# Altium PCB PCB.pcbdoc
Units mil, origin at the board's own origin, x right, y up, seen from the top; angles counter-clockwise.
Board outline 3858.27 x 1594.49 mil, 2 copper layers (Top Layer, Bottom Layer); 30 components, 23 nets, 84 pads, 0 vias.
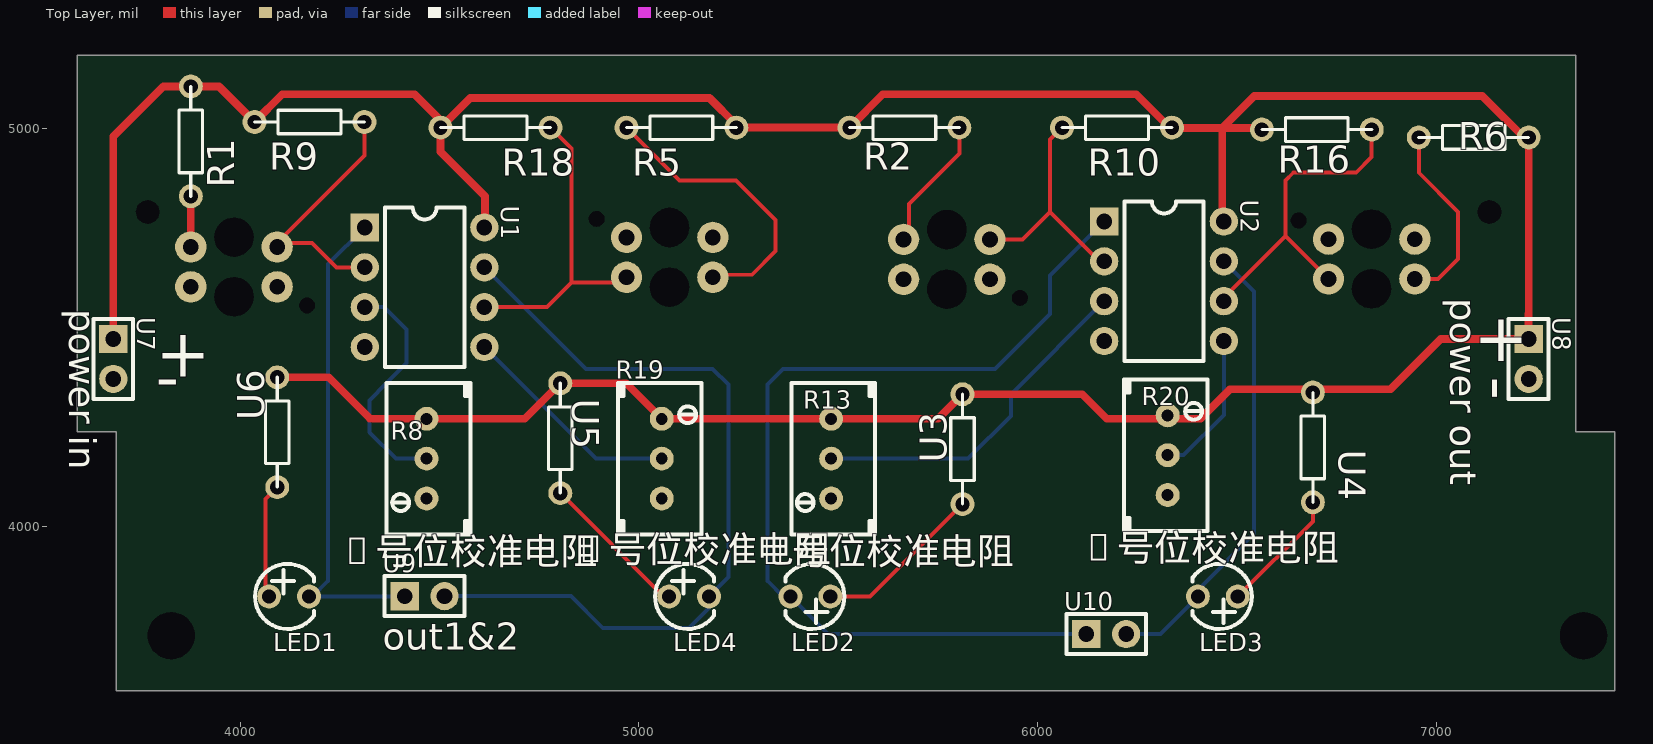
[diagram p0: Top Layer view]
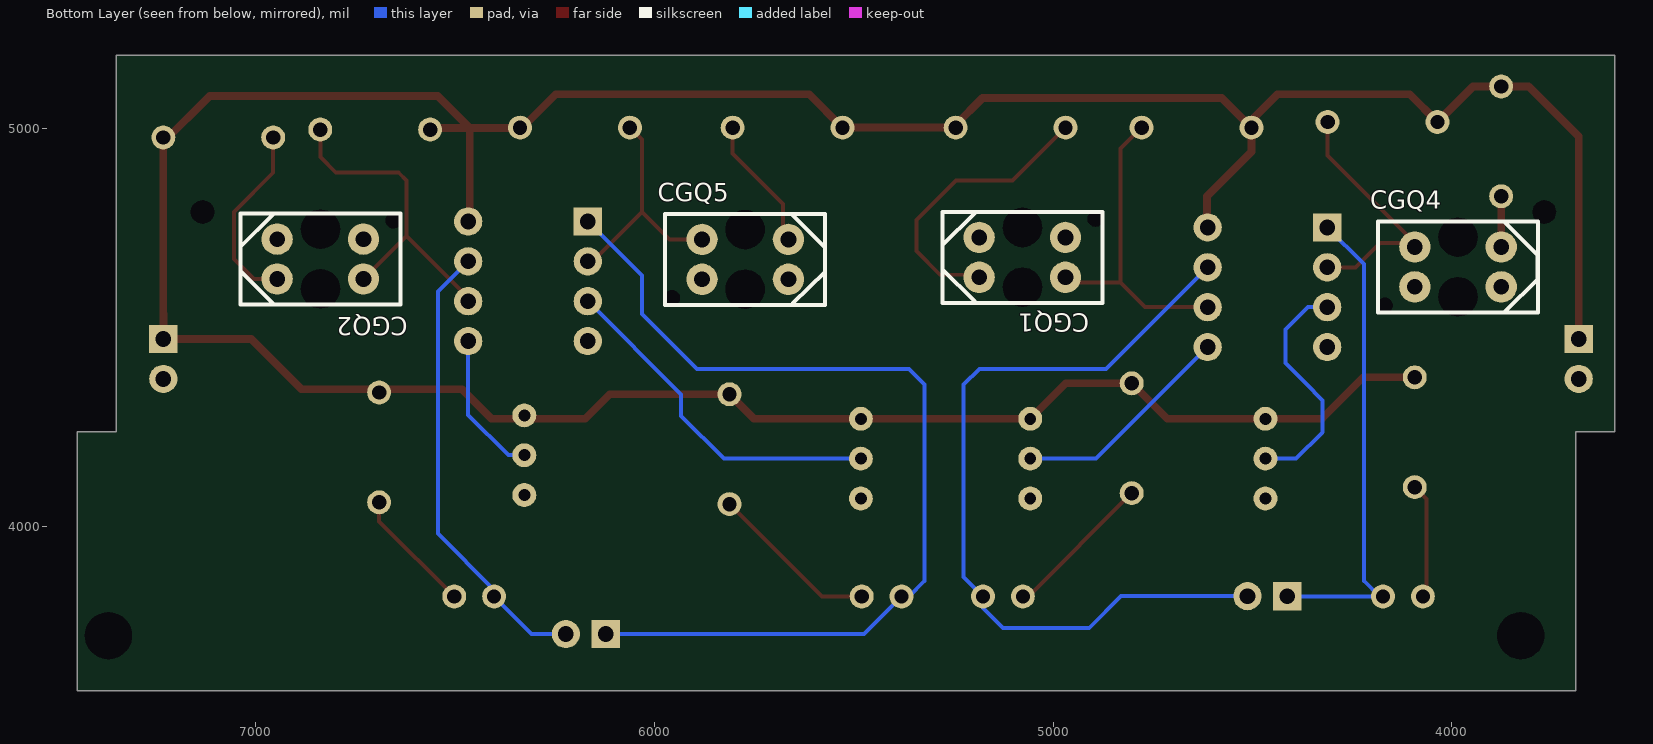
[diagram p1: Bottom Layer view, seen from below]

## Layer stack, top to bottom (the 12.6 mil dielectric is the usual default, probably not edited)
Top Solder: solder mask 0.4, Solder Resist, Dk 3.5
Top Layer: signal copper 1.4
Dielectric 1: dielectric 12.6, FR-4, Dk 4.8
Bottom Layer: signal copper 1.4
Bottom Solder: solder mask 0.4, Solder Resist, Dk 3.5

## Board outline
3590.55,5183.46 7350.39,5183.46 7350.39,4238.58 7448.82,4238.58 7448.82,3588.97 3688.98,3588.97 3688.98,4238.58 3590.55,4238.58
cut-out: 3885.83,3726.77 ccw(c3826.77,3726.77) 3767.72,3726.77 ccw(c3826.77,3726.77)
cut-out: 7429.13,3726.77 ccw(c7370.08,3726.77) 7311.02,3726.77 ccw(c7370.08,3726.77)
cut-out: 3797.24,4789.76 ccw(c3767.72,4789.76) 3738.19,4789.76 ccw(c3767.72,4789.76)
cut-out: 7163.39,4789.76 ccw(c7133.86,4789.76) 7104.33,4789.76 ccw(c7133.86,4789.76)

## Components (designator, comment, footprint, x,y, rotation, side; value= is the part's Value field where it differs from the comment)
CGQ1 "" opto-th_tcrt5000l 5077.44,4675.9 r0 bottom
CGQ2 "" opto-th_tcrt5000l 6838.58,4671.65 r0 bottom
CGQ4 "" opto-th_tcrt5000l 3984.25,4651.96 r180 bottom
CGQ5 "" opto-th_tcrt5000l 5772.44,4670.9 r180 bottom
LED1 "" led-th_bd3.8-p2.54-fd 4122.44,3825.19 r0 top
LED2 "" led-th_bd3.8-p2.54-fd 5430.31,3825.19 r180 top
LED3 "" led-th_bd3.8-p2.54-fd 6452.44,3825.19 r180 top
LED4 "" led-th_bd3.8-p2.54-fd 5125.98,3825.19 r0 top
R1 "" 直插电阻 3905.51,5045.66 r270 top
R2 "" 直插电阻 5587.44,5030.9 r0 top
R5 "" 直插电阻 5027.98,5030.9 r0 top
R6 "" 直插电阻 7015.75,5006.29 r0 top
R8 "1号位校准电阻" res-adj-th_3296w 4467.44,4170.9 r180 top
R9 "" 直插电阻 4252.44,4985.9 r180 top
R10 "" 直插电阻 6120.84,5030.9 r0 top
R13 "3号位校准电阻" res-adj-th_3296w 5482.44,4170.9 r180 top
R16 "" 直插电阻 6622.05,5025.98 r0 top
R18 "" 直插电阻 4561.56,5030.9 r0 top
R19 "2号位校准电阻" res-adj-th_3296w 5057.44,4170.9 r0 top
R20 "4号位校准电阻" res-adj-th_3296w 6326.77,4179.52 r0 top
U1 "" dip-8_l9.7-w6.4-p2.54-ls7.6-bl 4462.44,4600.9 r270 top
U2 "" dip-8_l9.7-w6.4-p2.54-ls7.6-bl 6317.44,4615.9 r270 top
U3 "" 直插电阻 5782.44,4115.9 r90 top
U4 "" 直插电阻 6720.47,4277.95 r270 top
U5 "" 直插电阻 4832.44,4300.9 r270 top
U6 "" 直插电阻 4122.44,4315.9 r270 top
U7 "power in" hdr-th_2p-p2.54-v-m-1 3681.5,4420.9 r270 top
U8 "power out" hdr-th_2p-p2.54-v-m-1 7232.28,4420.9 r270 top
U9 "out1&2" hdr-th_2p-p2.54-v-m-1 4462.44,3825.9 r0 top
U10 "" hdr-th_2p-p2.54-v-m-1 6172.44,3730.9 r0 top

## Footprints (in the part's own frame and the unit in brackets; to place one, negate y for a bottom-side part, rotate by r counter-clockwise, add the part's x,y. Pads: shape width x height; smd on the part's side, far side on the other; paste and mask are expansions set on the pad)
dip-8_l9.7-w6.4-p2.54-ls7.6-bl [mil]
  rect 70.9x70.9 hole 39.4: 1(-150,-150)
  round 70.9 hole 39.4: 2(-50,-150) 3(50,-150) 4(150,-150) 5(150,150) 6(50,150) 7(-50,150) 8(-150,150)
  silkscreen extent -200,-100 200,100
hdr-th_2p-p2.54-v-m-1 [mm]
  rect 1.8x1.8 hole 1: 1(-1.27,0)
  round 1.8 hole 1: 2(1.27,0)
  silkscreen extent -2.54,-1.27 2.54,1.27
led-th_bd3.8-p2.54-fd [mil]
  round 60 hole 35.43: 1(-50,0) 2(50,0)
  silkscreen extent -85,-82 63,82
opto-th_tcrt5000l [mil]
  round 78.7 hole 39.4: 1(-108.3,50) 2(-108.3,-50) 3(108.3,50) 4(108.3,-50)
  Multi-Layer board cut-out: 48.9,74.7 48.9,74.7 44.03,53.35 30.38,36.23 10.65,26.73 -11.25,26.73 -30.98,36.23 -44.63,53.35 -49.5,74.7 -49.5,74.7 -44.63,96.05 -30.98,113.17 -11.25,122.67 10.65,122.67 30.38,113.17 44.03,96.05 48.9,74.7
  Multi-Layer board cut-out: 48.9,-74.9 48.9,-74.9 44.03,-96.25 30.38,-113.37 10.65,-122.87 -11.25,-122.87 -30.98,-113.37 -44.63,-96.25 -49.5,-74.9 -49.5,-74.9 -44.63,-53.55 -30.98,-36.43 -11.25,-26.93 10.65,-26.93 30.38,-36.43 44.03,-53.55 48.9,-74.9
  Multi-Layer board cut-out: -163.7,-96.6 -163.7,-96.6 -165.65,-105.15 -171.12,-112 -179.02,-115.81 -187.78,-115.81 -195.68,-112 -201.15,-105.15 -203.1,-96.6 -203.1,-96.6 -201.15,-88.05 -195.68,-81.2 -187.78,-77.39 -179.02,-77.39 -171.12,-81.2 -165.65,-88.05 -163.7,-96.6
  silkscreen extent -201,-114 200,114
res-adj-th_3296w [mil]
  round 60 hole 30: 1(0,100) 2(0,0) 3(0,-100)
  silkscreen extent -110,-190 100,190
直插电阻 [mil]
  round 60 hole 36: 1(216.54,-29.53) 2(-59.06,-29.53)
  silkscreen extent -59,-59 217,0

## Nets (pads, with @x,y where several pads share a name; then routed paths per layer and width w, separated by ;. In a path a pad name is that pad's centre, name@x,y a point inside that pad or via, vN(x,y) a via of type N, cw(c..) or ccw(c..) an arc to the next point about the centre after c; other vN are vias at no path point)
$3N2055: CGQ4.3 R1.1 | length 117
  Top Layer w19.68: CGQ4.3@3875.86,4712.2 3875.98,4712.33 R1.1
$3N2059: CGQ5.3 R2.1 | length 338.4
  Top Layer w10: CGQ5.3 5677.17,4733.92 5677.17,4809.44 5803.98,4936.25 R2.1
$3N2549: CGQ1.3 R5.2 | length 732
  Top Layer w10: R5.2 5101.8,4868.5 5244.09,4868.5 5342.52,4770.07 5342.52,4691.33 5283.46,4632.28 5192.12,4632.28 CGQ1.3
$3N2554: CGQ2.3 R6.2 | length 474.8
  Top Layer w10: CGQ2.3 7005.12,4621.65 7055.12,4671.65 7055.12,4789.76 6956.69,4888.18 R6.2
$3N2706: CGQ4.1 R9.2 U1.2 | length 639.3
  Top Layer w10: R9.2 4311.5,4931.24 4092.46,4712.2 4179.92,4712.2 4241.22,4650.9 U1.2
$3N4107: CGQ5.1 R10.2 U2.2 | length 590.7
  Top Layer w10: CGQ5.1 5962.64,4720.9 6031.5,4789.76 ; R10.2 6031.5,4971.08 6031.5,4789.76 ; U2.2 6155.35,4665.9 6031.5,4789.76
$3N4588: R13.2 U2.3 | length 880
  Bottom Layer w10: R13.2 5826.02,4170.9 5933.07,4277.95 5933.07,4331.53 U2.3
$3N7184: CGQ2.1 R16.1 U2.6 | length 829.6
  Top Layer w10: U2.6 6467.44,4575.28 6622.05,4729.88 ; CGQ2.1 6622.05,4729.88 ; R16.1 6838.58,4927.55 6799.21,4888.18 6641.73,4888.18 6622.05,4868.5 6622.05,4729.88
$3N7213: CGQ1.1 R18.1 U1.6 | length 798.3
  Top Layer w10: U1.6 4769.02,4550.9 4830.71,4612.59 ; R18.1 4830.71,4948.75 4830.71,4612.59 ; CGQ1.1 4955.83,4612.59 4830.71,4612.59
$3N7681: R19.2 U1.5 | length 561
  Bottom Layer w10: U1.5 4892.44,4170.9 R19.2
$3N9269: R20.2 U2.5 | length 367.7
  Bottom Layer w10: R20.2 6366.14,4179.52 6467.44,4280.82 U2.5
$3N15684: LED1.1 U6.1 | length 290.5
  Top Layer w10: LED1.1 4062.99,3834.64 4062.99,4069.44 U6.1
$3N15894: LED2.1 U3.2 | length 427.6
  Top Layer w10: LED2.1 5580.31,3825.19 U3.2
$3N16954: LED3.1 U4.1 | length 314.3
  Top Layer w10: LED3.1 6690.94,4013.69 U4.1
$3N17558: LED4.1 U5.1 | length 380.4
  Top Layer w10: U5.1 5062.09,3825.19 LED4.1
$3N17687: R8.2 U1.3 | length 595.1
  Bottom Layer w10: U1.3 4360.91,4550.9 4417.32,4494.48 4417.32,4410.78 4367.44,4360.9 4323.74,4317.2 4323.74,4237.81 4325.94,4235.61 4390.65,4170.9 R8.2
GND: CGQ1.2 CGQ1.4 CGQ2.2 CGQ2.4 CGQ4.2 CGQ4.4 CGQ5.2 CGQ5.4 R8.1 R13.1 R19.3 R20.3 U1.4 U2.4 U7.2 U8.2
PIN1: LED1.2 U1.1 U9.1 | length 1232.7
  Bottom Layer w10: LED1.2@4172.44,3816.53 LED1.2@4181.1,3825.19 ; LED1.2 LED1.2@4181.1,3825.19 ; U1.1 4220.47,4658.93 4220.47,3864.56 LED1.2@4181.1,3825.19 ; U9.1 4411.73,3825.19 LED1.2@4181.1,3825.19
PIN2: LED4.2 U1.7 U9.2 | length 2031.3
  Bottom Layer w10: U9.2 4830,3825.9 4909.45,3746.45 5125.98,3746.45 5175.98,3796.45 LED4.2 5224.41,3873.62 5224.41,4356.69 5185.04,4396.06 4867.28,4396.06 U1.7
PIN3: LED2.2 U2.1 U10.1 | length 2417.5
  Bottom Layer w10: U10.1 5474.61,3730.9 LED2.2 5362.2,3825.19 5322.83,3864.56 5322.83,4356.69 5362.2,4396.06 5893.7,4396.06 6031.5,4533.85 6031.5,4629.96 U2.1
PIN4: LED3.2 U2.7 U10.2 | length 1149.5
  Bottom Layer w10: U10.2 6308.15,3730.9 LED3.2 6402.44,3841.81 6543.31,3982.67 6543.31,4590.03 U2.7
VCC: R1.2 R2.2 R5.1 R6.1 R8.3 R9.1 R10.1 R13.3 R16.2 R18.2 R19.1 R20.1 U1.8 U2.8 U3.1 U4.2 U5.2 U6.2 U7.1 U8.1 | length 8958.2
  Top Layer w19.68: U7.1 3681.5,4979.13 3807.09,5104.72 R1.2 3946.61,5104.72 R9.1 4105.51,5085.03 4437.01,5085.03 4502.5,5019.54 R18.2 ; U6.2 4221.89,4374.96 4325.94,4270.9 R8.3 4713.86,4270.9 U5.2 4968.39,4359.96 R19.1 R13.3 5750.43,4270.9 U3.1 6112.21,4332.44 6173.75,4270.9 6408.86,4270.9 6482.91,4344.96 6885.91,4344.96 7011.85,4470.9 U8.1 7232.28,4533.85 7232.44,4534.01 7232.44,4964.48 7116.02,5080.9 6543.94,5080.9 6463.46,5000.43 ; U1.8 4614.17,4752.63 4614.17,4829.13 4502.5,4940.8 R18.2 ; U2.8 6463.46,4769.88 6463.46,5000.43 ; R16.2 6559.02,5000.43 6463.46,5000.43 ; R18.2 4577.03,5075.9 5177.44,5075.9 5244.52,5008.82 R5.1 R2.2 5612.05,5085.03 6248.03,5085.03 6331.69,5001.37 R10.1 6338.32,5000.43 6463.46,5000.43
"": 

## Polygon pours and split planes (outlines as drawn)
GND on Top Layer (solid, remove dead copper, pour order 0): 3000,3077.16 7783.46,3077.16 7783.46,5675.58 3000,5675.58
GND on Bottom Layer (solid, remove dead copper, pour order 1): 3157.48,3254.33 8098.43,3254.33 8098.43,5557.47 3157.48,5557.47

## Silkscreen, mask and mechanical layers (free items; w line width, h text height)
Top Overlay:
  text "+" at 7094.49,4415.74 h120
  text "+" at 3787.4,4376.37 h120
  text "-" at 3787.4,4317.32 h120
  text "-" at 7192.91,4317.32 h120 r90
Mechanical 1:
  circle w1 net "": c3826.77,3726.77 r59.06
  circle w1 net "": c7370.08,3726.77 r59.06
  circle w1 net "": c3767.72,4789.76 r29.53
  circle w1 net "": c7133.86,4789.76 r29.53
